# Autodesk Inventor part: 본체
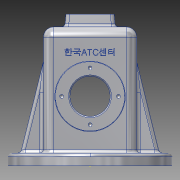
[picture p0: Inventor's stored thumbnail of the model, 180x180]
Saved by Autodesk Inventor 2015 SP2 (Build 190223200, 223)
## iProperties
Created: 2017-07
Part Number: 본체
Material: 알루미늄 6061
Document SubType Name: Modeling
Designer: Admin
Density: 2.7 g/cm^3
Appearance: 알루미늄 - 평지
Mass: 889.418 g
Surface Area: 987.354 cm^2
Volume: 329.414 cm^3
Author: Admin
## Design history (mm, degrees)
sketch "스케치1"
  geometry: L1 (75, 0)-(-75, 0); L2 (0, 0)-(0, -65); 2 further points; 1 other entity
  constraints: 4 end point, 2 coincident, 2 horizontal, 1 midpoint, 1 vertical, 4 other
  dimensions: "d1" = 150 distance of L1.start L1.end; "d2" = 65 distance of L2.start L2.end
extrude "돌출1" new body sketch "스케치1" distance "d3" = 10; taper "d4" = 0 deg
sketch "스케치2"
  geometry: L1 (-37, -37)-(37, -37); L2 (37, -37)-(37, 37); L3 (37, 37)-(-37, 37); L4 (-37, 37)-(-37, -37); L5 (-37, -37)-(37, 37); L6 (37, -37)-(-37, 37); 1 further point
  constraints: 12 end point, 2 midpoint, 2 parallel, 1 horizontal, 1 perpendicular
  dimensions: "d5" = 74 distance of L3.end L2.end; "d6" = 74 distance of L2.end L1.end
extrude "돌출2" join sketch "스케치2" distance "d7" = 100; taper "d8" = 0 deg
sketch "스케치3"
  geometry: L1 (-32, 0)-(32, 0); L2 (37, 110)-(-37, 110) reference; L3 (32, 105)-(-32, 105); L4 (0, 55)-(-32, 55); L5 (-32, 55)-(-32, 82.5); L6 (-37, 10)-(-37, 110) reference; L7 (-25, 55)-(-25, 75.5); L8 (-32, 82.5)-(-25, 75.5); L9 (25, 55)-(25, 75.5); L10 (32, 82.5)-(25, 75.5); L11 (0, 55)-(32, 55); L12 (-25, 55)-(-32, 55); L13 (25, 55)-(32, 55); L14 (-32, 55)-(-32, 82.5); L15 (-32, 82.5)-(-25, 75.5); L16 (-25, 55)-(-25, 75.5); L17 (25, 55)-(25, 75.5); L18 (25, 75.5)-(32, 82.5); L19 (32, 82.5)-(32, 55); L20 (-32, 55)-(-32, 82.5); L21 (-32, 82.5)-(-25, 75.5); L22 (-32, 55)-(-25, 55); L23 (32, 55)-(25, 55); L24 (25, 55)-(25, 75.5); L25 (25, 75.5)-(32, 82.5); L26 (32, 82.5)-(32, 55); L27 (-25, 55)-(25, 55); L28 (-32, 55)-(32, 55); L29 (-32, 82.5)-(-32, 105); L30 (32, 82.5)-(32, 105); L31 (-32, 55)-(-32, 0); L32 (32, 55)-(32, 0); L33 (-32, 55)-(-25, 55); L34 (-25, 55)-(-25, 75.5); L35 (-25, 75.5)-(-32, 82.5); L36 (-32, 82.5)-(-32, 55); L37 (32, 55)-(25, 55); L38 (25, 55)-(25, 75.5); L39 (25, 75.5)-(32, 82.5); 1 further point
  constraints: 74 end point, 7 horizontal, 7 perpendicular, 5 vertical, 4 parallel, 3 collinear, 2 point on line
  dimensions: "d10" = 5 distance between parallel lines of L2 L3; "d12" = 27.5 distance of L4.end L5.end; "d17" = 55 distance between parallel lines of L4 L2; "d20" = 15.9099 distance from line of L2.start L10; "d21" = 27.5 distance from line of L10.start L2; "d23" = 37 distance from line of L4.start L6; "d24" = 135 deg angle of L6 L8; "d27" = 90 deg angle of L26 L2; "d28" = 110 distance between parallel lines of L1 L2; "d29" = 62 distance between parallel lines of L38 L6; "d30" = 12 distance between parallel lines of L34 L6; "d31" = 5 distance between parallel lines of L31 L6
extrude "돌출3" cut sketch "스케치3" stored distance "d25" = 64; taper "d26" = 0 deg
sketch "스케치4"
  geometry: L1 (0, 0)-(0, 55); L2 (0, 55)-(-50, 55); L3 (-50, 55)-(-50, 82.5); L4 (-37, 10)-(-37, 110) reference; L5 (-32, 0)-(-32, 105) reference; L6 (-50, 82.5)-(-32, 82.5); L7 (-32, 82.5)-(-25, 75.5); L8 (-25, 55)-(-25, 75.5); L9 (-50, 55)-(-50, 71); L10 (-50, 71)-(-25, 71)
  constraints: 16 end point, 3 point on line, 2 perpendicular, 2 vertical, 1 horizontal, 1 midpoint, 1 parallel
  dimensions: "d32" = 55 distance of L1.start L1.end; "d33" = 50 distance of L1.end L2.end; "d34" = 27.5 distance of L2.end L3.end; "d35" = 135 deg angle of L4 L7; "d36" = 7 distance between parallel lines of L5 L8; "d37" = 16 distance of L2.end L9.end
revolve "회전1" stored, may be unused: angle "d38" = 90 deg
revolve "회전2" stored, may be unused: angle "d39" = 90 deg
sketch "스케치5"
  geometry: L1 (-20, 110)-(20, 110); L2 (37, 110)-(-37, 110) reference; L3 (-20, 110)-(-19.125, 120); L4 (20, 110)-(19.125, 120); L5 (-37, 10)-(-37, 110) reference; L6 (37, 10)-(37, 110) reference; L7 (-19.125, 120)-(19.125, 120); 2 further points
  constraints: 8 end point, 2 midpoint, 1 horizontal
  dimensions: "d40" = 40 distance of L1.start L1.end; "d41" = 5 deg angle of L3 L5; "d42" = 5 deg angle of L4 L6; "d43" = 10 distance between parallel lines of L2 L7
extrude "돌출4" join sketch "스케치5" stored distance "d44" = 40; taper "d45" = 0 deg
sketch "스케치6"
  geometry: L1 (10, 37)-(110, 37) reference; L2 (110, -37)-(110, 37) reference; L3 (120, 20)-(110, 20) reference; L4 (110, 20)-(120, 19.125); L5 (110, -20)-(120, -20) reference; L6 (110, -20)-(120, -19.125); L7 (10, -37)-(110, -37) reference; L8 (120, -20)-(120, 20) reference; 1 further point
  constraints: 4 end point, 2 point on line
  dimensions: "d46" = 5 deg angle of L4 L1; "d47" = 5 deg angle of L6 L7
extrude "돌출5" cut sketch "스케치6" stored distance "d48" = 40; taper "d49" = 0 deg
sketch "스케치7"
  geometry: L1 (0, 0)-(0, 22.5); C1 r 27.5 at (0, 0) reference; 2 further points
  constraints: 2 end point, 1 coincident, 1 vertical
  dimensions: "d50" = 22.5 distance of L1.start L1.end
hole "구멍1" sketch "스케치7" at (0, 22.5) diameter "d51" = 3.242; stored, may be unused: countersink angle "d55" = 90 deg, drill point angle "d57" = 118 deg; dims "d52" = 8, "d53" = 4, "d54" = 2, "d56" = 10
sketch "스케치8"
  geometry: 2 further points
  constraints: 1 coincident
hole "구멍2" sketch "스케치8" at (19.125, 19.125) diameter "d61" = 21; stored, may be unused: countersink angle "d65" = 90 deg, drill point angle "d67" = 0 deg; dims "d62" = 8, "d63" = 28, "d64" = 4, "d66" = 30
sketch "스케치9"
  geometry: L1 (-58, 0)-(58, 0); 4 further points
  constraints: 3 coincident, 2 end point, 1 horizontal, 1 midpoint
  dimensions: "d68" = 116 distance of L1.start L1.end
hole "구멍3" sketch "스케치9" at (-58, 0), (58, 0) diameter "d69" = 10; stored, may be unused: countersink angle "d73" = 90 deg, drill point angle "d75" = 0 deg; dims "d70" = 8, "d71" = 28, "d72" = 4, "d74" = 30
sketch "스케치10"
  geometry: L1 (10, 55)-(85.176, 36.256)
  constraints: 2 end point
  dimensions: "d86" = 75.1765 horizontal distance of L1.start L1.end
feature "리브1" sketch "스케치10" dims "d94" = 1, "d95" = 10, "d96" = 0, "d97" = 0, "d98" = 1, "d99" = 1
fillet "모깎기1" dims "d100" = 0.5, "d101" = 3, "d102" = 8
chamfer "모따기1" distance "d103" = 1; stored, may be unused: second distance "d104" = 2, angle "d105" = 45 deg
sketch "스케치11"
  geometry: L1 (-12.863, 107)-(-45.137, 107) reference; L2 (-29, 107)-(-29, 77); 2 further points
  constraints: 2 end point, 1 coincident, 1 midpoint, 1 vertical, 1 other
  dimensions: "d106" = 30 distance of L2.start L2.end
feature "엠보싱1" sketch "스케치11" dims "d1" = 150, "d2" = 65, "d12" = 27.5, "d107" = 0.5, "d108" = 0
sketch "스케치12"
  geometry: 1 further point
node "솔리드1"
mirror "대칭1"
pattern_circular "원형 패턴1" dims angle "d59" = 360 deg
mirror "대칭2"
mirror "대칭3"
